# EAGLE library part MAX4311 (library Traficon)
High-Speed, Low-Power, Single-Supply Multichannel, Video Multiplexer-Amplifiers
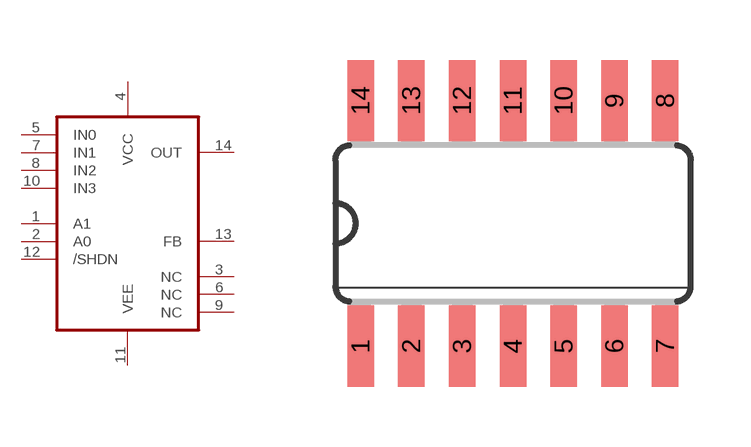
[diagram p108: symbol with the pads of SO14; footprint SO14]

Designator prefix -

## MAX4311ESD  [SO14]
1  A1
2  A0
3  NC
4  VCC
5  IN0
6  NC
7  IN1
8  IN2
9  NC
10  IN3
11  VEE
12  /SHDN
13  FB
14  OUT

## Footprint SO14 (pad centres in mm)
Small Outline package 150 mil
smd 0.66 x 2.032: 1 -3.81,-3.073; 2 -2.54,-3.073; 3 -1.27,-3.073; 4 0,-3.073; 5 1.27,-3.073; 6 2.54,-3.073; 7 3.81,-3.073; 8 3.81,3.073; 9 2.54,3.073; 10 1.27,3.073; 11 0,3.073; 12 -1.27,3.073; 13 -2.54,3.073; 14 -3.81,3.073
